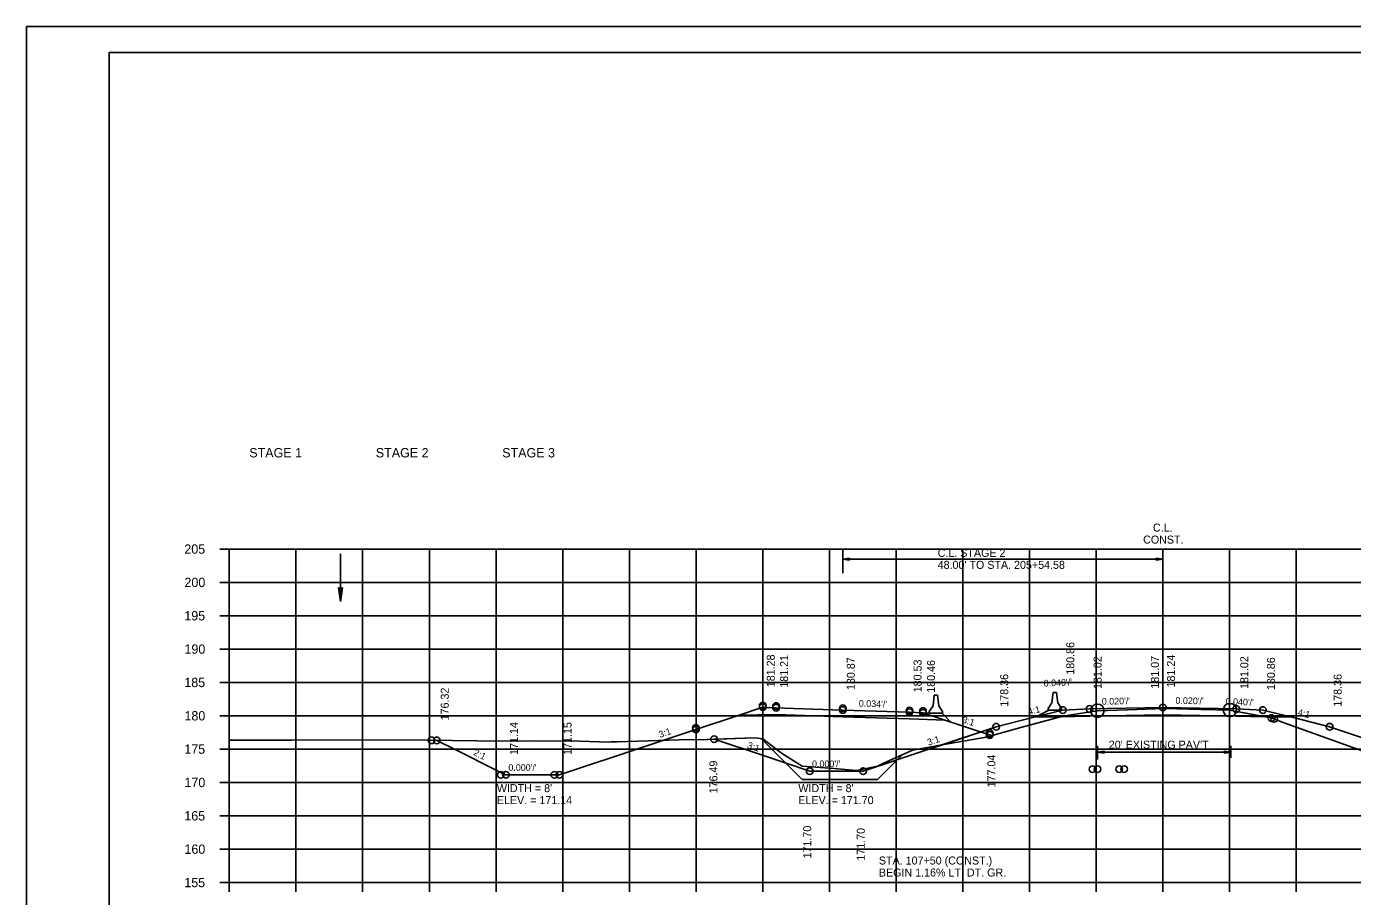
# Model space of a CAD drawing. Extents: x 1372132 to 1372465, y 380083 to 381790.
# Drawn here: x 1372131.6 to 1372330.4, y 381019.7 to 381150.2 of the extents above; entities that cross this region are included whole.
import ezdxf

# ---------------------------------------------------------------- set-up
doc = ezdxf.new("R2010")
doc.units = 0
for name, color, linetype in [('R_Alt Surface', 7, 'Continuous'), ('R_Axis', 7, 'Continuous'), ('R_Axis Annot', 7, 'Continuous'), ('R_Border', 7, 'Continuous'), ('R_Dimension', 7, 'Continuous'), ('R_Draft', 7, 'Continuous'), ('R_Erosion', 7, 'Continuous'), ('R_Exist Surface', 7, 'Continuous'), ('R_Fin Surface', 7, 'Continuous'), ('R_Grid', 7, 'Continuous'), ('R_No Plot', 7, 'Continuous'), ('R_Xsect Elev', 7, 'Continuous'), ('R_Xsect Slope', 7, 'Continuous')]:
    doc.layers.add(name, color=color, linetype=linetype)

msp = doc.modelspace()

# ---------------------------------------------------------------- linework, layer by layer
at = {"layer": 'R_Alt Surface'}
for points in [[(1372269.37, 381046.17), (1372264.02, 381046.35), (1372254.01, 381046.69), (1372244, 381047.04), (1372238.46, 381046.93)], [(1372321.38, 381046.6), (1372313.01, 381046.76), (1372302.01, 381046.98), (1372291.01, 381046.76), (1372282.65, 381046.6)]]:
    msp.add_lwpolyline(points, dxfattribs=at)
at = {"layer": 'R_Axis'}
for p, q in [((1372160.61, 381071.83), (1372162.01, 381071.83)), ((1372162.01, 381021.83), (1372162.01, 381071.83)), ((1372160.61, 381066.83), (1372162.01, 381066.83)), ((1372160.61, 381061.83), (1372162.01, 381061.83)), ((1372160.61, 381056.83), (1372162.01, 381056.83)), ((1372160.61, 381051.83), (1372162.01, 381051.83)), ((1372160.61, 381046.83), (1372162.01, 381046.83)), ((1372160.61, 381041.83), (1372162.01, 381041.83)), ((1372160.61, 381036.83), (1372162.01, 381036.83)), ((1372160.61, 381031.83), (1372162.01, 381031.83)), ((1372160.61, 381026.83), (1372162.01, 381026.83)), ((1372160.61, 381021.83), (1372162.01, 381021.83)), ((1372162.01, 381021.83), (1372442.01, 381021.83)), ((1372162.01, 381020.43), (1372162.01, 381021.83)), ((1372172.01, 381020.43), (1372172.01, 381021.83)), ((1372182.01, 381020.43), (1372182.01, 381021.83)), ((1372192.01, 381020.43), (1372192.01, 381021.83)), ((1372202.01, 381020.43), (1372202.01, 381021.83)), ((1372212.01, 381020.43), (1372212.01, 381021.83)), ((1372222.01, 381020.43), (1372222.01, 381021.83)), ((1372232.01, 381020.43), (1372232.01, 381021.83)), ((1372242.01, 381020.43), (1372242.01, 381021.83)), ((1372252.01, 381020.43), (1372252.01, 381021.83)), ((1372262.01, 381020.43), (1372262.01, 381021.83)), ((1372272.01, 381020.43), (1372272.01, 381021.83)), ((1372282.01, 381020.43), (1372282.01, 381021.83)), ((1372292.01, 381020.43), (1372292.01, 381021.83)), ((1372302.01, 381020.43), (1372302.01, 381021.83)), ((1372312.01, 381020.43), (1372312.01, 381021.83)), ((1372322.01, 381020.43), (1372322.01, 381021.83))]:
    msp.add_line(p, q, dxfattribs=at)
at = {"layer": 'R_Border'}
for p, q in [((1372144.01, 381146.29), (1372460.19, 381146.29)), ((1372144.01, 380940.83), (1372144.01, 381146.29)), ((1372296.53, 381146.03), (1372296.53, 381146.03)), ((1372296.53, 381146.03), (1372296.53, 381146.03))]:
    msp.add_line(p, q, dxfattribs=at)
at = {"layer": 'R_Dimension'}
for p, q in [((1372178.41, 381065.99), (1372178.71, 381063.99)), ((1372179.01, 381065.99), (1372178.41, 381065.99)), ((1372178.41, 381065.99), (1372178.71, 381063.99)), ((1372179.01, 381065.99), (1372178.41, 381065.99)), ((1372178.46, 381065.99), (1372178.71, 381064.32)), ((1372178.46, 381065.99), (1372178.71, 381064.32)), ((1372178.51, 381065.99), (1372178.71, 381064.67)), ((1372178.51, 381065.99), (1372178.71, 381064.67)), ((1372178.56, 381065.99), (1372178.71, 381065)), ((1372178.56, 381065.99), (1372178.71, 381065)), ((1372178.61, 381065.99), (1372178.71, 381065.34)), ((1372178.61, 381065.99), (1372178.71, 381065.34)), ((1372178.66, 381065.99), (1372178.71, 381065.67)), ((1372178.66, 381065.99), (1372178.71, 381065.67)), ((1372179.01, 381065.99), (1372178.71, 381063.99)), ((1372178.8, 381065.99), (1372178.71, 381065.34)), ((1372178.91, 381065.99), (1372178.71, 381064.67)), ((1372178.96, 381065.99), (1372178.71, 381064.32)), ((1372178.86, 381065.99), (1372178.71, 381065)), ((1372178.75, 381065.99), (1372178.71, 381065.67)), ((1372179.01, 381065.99), (1372178.71, 381063.99)), ((1372178.8, 381065.99), (1372178.71, 381065.34)), ((1372178.91, 381065.99), (1372178.71, 381064.67)), ((1372178.96, 381065.99), (1372178.71, 381064.32)), ((1372178.86, 381065.99), (1372178.71, 381065)), ((1372178.75, 381065.99), (1372178.71, 381065.67))]:
    msp.add_line(p, q, dxfattribs=at)
at = {"layer": 'R_Draft'}
for p, q in [((1372178.71, 381071.13), (1372178.71, 381063.99)), ((1372254.01, 381068.23), (1372254.01, 381071.83)), ((1372302.01, 381071.83), (1372302.01, 381068.23)), ((1372255.01, 381070.46), (1372254.01, 381070.31)), ((1372254.01, 381070.31), (1372302.01, 381070.31)), ((1372255.01, 381070.16), (1372254.01, 381070.31)), ((1372255.01, 381070.44), (1372254.18, 381070.31)), ((1372255.01, 381070.19), (1372254.18, 381070.31)), ((1372255.01, 381070.41), (1372254.35, 381070.31)), ((1372255.01, 381070.21), (1372254.35, 381070.31)), ((1372255.01, 381070.39), (1372254.52, 381070.31)), ((1372255.01, 381070.24), (1372254.52, 381070.31)), ((1372255.01, 381070.36), (1372254.69, 381070.31)), ((1372255.01, 381070.27), (1372254.69, 381070.31)), ((1372255.01, 381070.34), (1372254.85, 381070.31)), ((1372255.01, 381070.29), (1372254.85, 381070.31)), ((1372255.01, 381070.16), (1372255.01, 381070.46)), ((1372301.01, 381070.46), (1372302.01, 381070.31)), ((1372301.01, 381070.46), (1372301.01, 381070.16)), ((1372301.01, 381070.46), (1372302.01, 381070.31)), ((1372301.01, 381070.46), (1372301.01, 381070.16)), ((1372301.01, 381070.44), (1372301.85, 381070.31)), ((1372301.01, 381070.44), (1372301.85, 381070.31)), ((1372301.01, 381070.41), (1372301.68, 381070.31)), ((1372301.01, 381070.41), (1372301.68, 381070.31)), ((1372301.01, 381070.39), (1372301.51, 381070.31)), ((1372301.01, 381070.39), (1372301.51, 381070.31)), ((1372301.01, 381070.36), (1372301.34, 381070.31)), ((1372301.01, 381070.36), (1372301.34, 381070.31)), ((1372301.01, 381070.34), (1372301.17, 381070.31)), ((1372301.01, 381070.34), (1372301.17, 381070.31)), ((1372301.01, 381070.16), (1372302.01, 381070.31)), ((1372301.01, 381070.26), (1372301.34, 381070.31)), ((1372301.01, 381070.21), (1372301.68, 381070.31)), ((1372301.01, 381070.19), (1372301.85, 381070.31)), ((1372301.01, 381070.24), (1372301.51, 381070.31)), ((1372301.01, 381070.29), (1372301.17, 381070.31)), ((1372301.01, 381070.16), (1372302.01, 381070.31)), ((1372301.01, 381070.26), (1372301.34, 381070.31)), ((1372301.01, 381070.21), (1372301.68, 381070.31)), ((1372301.01, 381070.19), (1372301.85, 381070.31)), ((1372301.01, 381070.24), (1372301.51, 381070.31)), ((1372301.01, 381070.29), (1372301.17, 381070.31)), ((1372267.72, 381049.9), (1372267.55, 381048.32)), ((1372267.72, 381049.9), (1372268.22, 381049.9)), ((1372268.4, 381048.32), (1372268.22, 381049.9)), ((1372285.55, 381050.34), (1372285.37, 381048.76)), ((1372285.55, 381050.34), (1372286.05, 381050.34)), ((1372286.23, 381048.76), (1372286.05, 381050.34)), ((1372267.55, 381048.32), (1372266.97, 381047.49)), ((1372266.97, 381047.24), (1372266.97, 381047.49)), ((1372266.97, 381047.24), (1372268.97, 381047.24)), ((1372268.97, 381047.49), (1372268.4, 381048.32)), ((1372268.97, 381047.24), (1372268.97, 381047.49)), ((1372285.37, 381048.76), (1372284.8, 381047.92)), ((1372284.8, 381047.67), (1372284.8, 381047.92)), ((1372284.8, 381047.67), (1372286.8, 381047.67)), ((1372286.8, 381047.92), (1372286.23, 381048.76)), ((1372286.8, 381047.67), (1372286.8, 381047.92)), ((1372292.19, 381042.3), (1372292.19, 381040.29)), ((1372293.19, 381041.53), (1372292.19, 381041.38)), ((1372293.19, 381041.53), (1372292.19, 381041.38)), ((1372312.17, 381041.38), (1372292.19, 381041.38)), ((1372293.19, 381041.23), (1372292.19, 381041.38)), ((1372293.19, 381041.23), (1372292.19, 381041.38)), ((1372293.19, 381041.51), (1372292.36, 381041.38)), ((1372293.19, 381041.51), (1372292.36, 381041.38)), ((1372293.19, 381041.26), (1372292.36, 381041.38)), ((1372293.19, 381041.26), (1372292.36, 381041.38)), ((1372293.19, 381041.48), (1372292.53, 381041.38)), ((1372293.19, 381041.48), (1372292.53, 381041.38)), ((1372293.19, 381041.28), (1372292.53, 381041.38)), ((1372293.19, 381041.28), (1372292.53, 381041.38)), ((1372293.19, 381041.46), (1372292.7, 381041.38)), ((1372293.19, 381041.46), (1372292.7, 381041.38)), ((1372293.19, 381041.31), (1372292.7, 381041.38)), ((1372293.19, 381041.31), (1372292.7, 381041.38)), ((1372293.19, 381041.43), (1372292.87, 381041.38)), ((1372293.19, 381041.43), (1372292.87, 381041.38)), ((1372293.19, 381041.33), (1372292.87, 381041.38)), ((1372293.19, 381041.33), (1372292.87, 381041.38)), ((1372293.19, 381041.4), (1372293.03, 381041.38)), ((1372293.19, 381041.4), (1372293.03, 381041.38)), ((1372293.19, 381041.36), (1372293.03, 381041.38)), ((1372293.19, 381041.36), (1372293.03, 381041.38)), ((1372293.19, 381041.23), (1372293.19, 381041.53)), ((1372293.19, 381041.23), (1372293.19, 381041.53)), ((1372311.17, 381041.53), (1372312.17, 381041.38)), ((1372311.17, 381041.53), (1372311.17, 381041.23)), ((1372311.17, 381041.51), (1372312, 381041.38)), ((1372311.17, 381041.48), (1372311.83, 381041.38)), ((1372311.17, 381041.46), (1372311.67, 381041.38)), ((1372311.17, 381041.43), (1372311.5, 381041.38)), ((1372311.17, 381041.4), (1372311.33, 381041.38)), ((1372311.17, 381041.23), (1372312.17, 381041.38)), ((1372311.17, 381041.33), (1372311.5, 381041.38)), ((1372311.17, 381041.28), (1372311.83, 381041.38)), ((1372311.17, 381041.26), (1372312, 381041.38)), ((1372311.17, 381041.31), (1372311.67, 381041.38)), ((1372311.17, 381041.36), (1372311.33, 381041.38)), ((1372312.17, 381042.3), (1372312.17, 381040.52)), ((1372292.19, 381040.52), (1372292.19, 381040.52))]:
    msp.add_line(p, q, dxfattribs=at)
at = {"layer": 'R_Erosion'}
for p, q in [((1372268.95, 381047.15), (1372266.03, 381047.28)), ((1372284.81, 381047.6), (1372283.09, 381046.74)), ((1372287.01, 381047.69), (1372284.81, 381047.6)), ((1372268.95, 381047.15), (1372270.22, 381045.89)), ((1372247.89, 381037.28), (1372241.76, 381043.4)), ((1372259.22, 381037.28), (1372262.92, 381040.98)), ((1372247.89, 381037.28), (1372259.22, 381037.28))]:
    msp.add_line(p, q, dxfattribs=at)
at = {"layer": 'R_Exist Surface'}
msp.add_lwpolyline([(1372162.01, 381043.18), (1372162.71, 381043.18), (1372171.37, 381043.15), (1372182.03, 381043.22), (1372191.65, 381043.16), (1372202.97, 381043.04), (1372207.47, 381043.06), (1372214.53, 381043.01), (1372218.9, 381042.87), (1372219.25, 381042.9), (1372220.16, 381042.9), (1372229.46, 381043.21), (1372233.7, 381043.28), (1372240.81, 381043.52), (1372242.03, 381043.37), (1372244.83, 381041.2), (1372247.9, 381039.27), (1372251.33, 381039.03), (1372252.16, 381038.98), (1372256.01, 381038.65), (1372256.58, 381038.74), (1372259.22, 381039.28), (1372260.03, 381039.65), (1372264.47, 381041.69), (1372268.93, 381042.46), (1372275.51, 381043.64), (1372280.69, 381045.09), (1372286.98, 381046.77), (1372289.51, 381047.15), (1372292.19, 381047.59), (1372296.69, 381047.72), (1372302.23, 381047.9), (1372307.74, 381047.78), (1372312.05, 381047.69), (1372317.93, 381046.57), (1372318.37, 381046.48), (1372320.06, 381045.84), (1372333.14, 381041.1)], dxfattribs=at)
at = {"layer": 'R_Fin Surface'}
for points in [[(1372193.12, 381043.14), (1372193.55, 381042.93), (1372195.57, 381041.92), (1372202.54, 381038.45), (1372203.5, 381037.97), (1372209.96, 381037.97), (1372211.53, 381037.97), (1372224.02, 381042.13), (1372231.99, 381044.78), (1372238.15, 381046.83), (1372242, 381048.11), (1372242.64, 381048.08), (1372244, 381048.04), (1372246.59, 381047.94), (1372254.01, 381047.69), (1372262.29, 381047.41), (1372263.87, 381047.36), (1372264.02, 381047.35), (1372265.95, 381047.29), (1372266.03, 381047.28), (1372274.77, 381044.37), (1372276.04, 381043.95), (1372276.31, 381043.86)], [(1372234.7, 381043.31), (1372241.96, 381040.9), (1372249.04, 381038.53), (1372257.04, 381038.53), (1372267.08, 381041.86), (1372277.01, 381045.19), (1372282.65, 381046.6), (1372287.01, 381047.69), (1372291.01, 381047.85), (1372302.01, 381048.07), (1372313.01, 381047.85), (1372317.01, 381047.69), (1372321.38, 381046.6), (1372327.01, 381045.19), (1372336.47, 381042.02), (1372346.07, 381038.83), (1372350.07, 381038.83), (1372354.63, 381040.37), (1372359.6, 381042.02), (1372359.73, 381042.05)]]:
    msp.add_lwpolyline(points, dxfattribs=at)
at = {"layer": 'R_Grid'}
for p, q in [((1372162.01, 381071.83), (1372442.01, 381071.83)), ((1372162.01, 381021.83), (1372162.01, 381071.83)), ((1372172.01, 381021.83), (1372172.01, 381071.83)), ((1372182.01, 381021.83), (1372182.01, 381071.83)), ((1372192.01, 381021.83), (1372192.01, 381071.83)), ((1372202.01, 381021.83), (1372202.01, 381071.83)), ((1372212.01, 381021.83), (1372212.01, 381071.83)), ((1372222.01, 381021.83), (1372222.01, 381071.83)), ((1372232.01, 381021.83), (1372232.01, 381071.83)), ((1372242.01, 381021.83), (1372242.01, 381071.83)), ((1372252.01, 381021.83), (1372252.01, 381071.83)), ((1372262.01, 381021.83), (1372262.01, 381071.83)), ((1372272.01, 381021.83), (1372272.01, 381071.83)), ((1372282.01, 381021.83), (1372282.01, 381071.83)), ((1372292.01, 381021.83), (1372292.01, 381071.83)), ((1372302.01, 381021.83), (1372302.01, 381071.83)), ((1372312.01, 381021.83), (1372312.01, 381071.83)), ((1372322.01, 381021.83), (1372322.01, 381071.83)), ((1372162.01, 381066.83), (1372442.01, 381066.83)), ((1372162.01, 381061.83), (1372442.01, 381061.83)), ((1372162.01, 381056.83), (1372442.01, 381056.83)), ((1372162.01, 381051.83), (1372442.01, 381051.83)), ((1372162.01, 381046.83), (1372442.01, 381046.83)), ((1372162.01, 381041.83), (1372442.01, 381041.83)), ((1372162.01, 381036.83), (1372442.01, 381036.83)), ((1372162.01, 381031.83), (1372442.01, 381031.83)), ((1372162.01, 381026.83), (1372442.01, 381026.83)), ((1372162.01, 381021.83), (1372442.01, 381021.83))]:
    msp.add_line(p, q, dxfattribs=at)
at = {"layer": 'R_No Plot'}
msp.add_line((1372131.61, 381150.18), (1372464.95, 381150.18), dxfattribs=at)
for points in [[(1372131.61, 381150.18), (1372464.95, 381150.18), (1372464.95, 380936.84), (1372131.61, 380936.84)], [(1372377.93, 381146.29), (1372377.93, 381136.41), (1372413.67, 381136.41), (1372413.67, 381133.49), (1372436.87, 381133.49), (1372436.87, 381109.15), (1372460.19, 381109.15), (1372460.19, 380940.83), (1372144.01, 380940.83), (1372144.01, 381146.29)], [(1372286.64, 381046.68), (1372286.98, 381046.77), (1372289.51, 381047.15), (1372292.19, 381047.59), (1372296.69, 381047.72), (1372302.23, 381047.9), (1372307.74, 381047.78), (1372312.05, 381047.69), (1372317.36, 381046.68), (1372313.01, 381046.76), (1372302.01, 381046.98), (1372291.01, 381046.76)], [(1372268.81, 381042.44), (1372268.93, 381042.46), (1372275.51, 381043.64), (1372280.69, 381045.09), (1372286.64, 381046.68), (1372282.65, 381046.6), (1372277.01, 381045.19)], [(1372317.36, 381046.68), (1372317.93, 381046.57), (1372318.37, 381046.48), (1372320.06, 381045.84), (1372333.14, 381041.1), (1372335.96, 381039.94), (1372337.86, 381039.25), (1372338.93, 381039.46), (1372341.58, 381040.33), (1372336.47, 381042.02), (1372327.01, 381045.19), (1372321.38, 381046.6)], [(1372234.7, 381043.31), (1372240.81, 381043.52), (1372242.03, 381043.37), (1372244.83, 381041.2), (1372247.9, 381039.27), (1372251.33, 381039.03), (1372252.16, 381038.98), (1372256.01, 381038.65), (1372256.58, 381038.74), (1372259.22, 381039.28), (1372260.03, 381039.65), (1372264.47, 381041.69), (1372268.81, 381042.44), (1372267.08, 381041.86), (1372257.04, 381038.53), (1372249.04, 381038.53), (1372241.96, 381040.9)]]:
    msp.add_lwpolyline(points, close=True, dxfattribs=at)
for centre, radius in [((1372242, 381048.36), 0.5), ((1372242, 381048.11), 0.5), ((1372244, 381048.29), 0.5), ((1372244, 381048.04), 0.5), ((1372254.01, 381047.95), 0.5), ((1372254.01, 381047.69), 0.5), ((1372264.02, 381047.6), 0.5), ((1372264.02, 381047.35), 0.5), ((1372266.03, 381047.54), 0.5), ((1372266.03, 381047.28), 0.5), ((1372287.01, 381047.69), 0.5), ((1372291.01, 381047.85), 0.5), ((1372292.19, 381047.59), 1), ((1372302.01, 381048.07), 0.5), ((1372312.05, 381047.69), 1), ((1372313.01, 381047.85), 0.5), ((1372317.01, 381047.69), 0.5), ((1372231.99, 381045.03), 0.5), ((1372231.99, 381044.78), 0.5), ((1372277.01, 381045.19), 0.5), ((1372318.31, 381046.49), 0.5), ((1372318.7, 381046.37), 0.5), ((1372327.01, 381045.19), 0.5), ((1372192.34, 381043.15), 0.5), ((1372193.12, 381043.14), 0.5), ((1372234.7, 381043.31), 0.5), ((1372276.04, 381044.2), 0.5), ((1372276.04, 381043.95), 0.5), ((1372291.45, 381038.82), 0.5), ((1372292.21, 381038.82), 0.5), ((1372295.44, 381038.83), 0.5), ((1372296.2, 381038.83), 0.5), ((1372202.74, 381037.97), 0.5), ((1372203.5, 381037.97), 0.5), ((1372210.76, 381037.97), 0.5), ((1372211.53, 381037.97), 0.5), ((1372249.04, 381038.53), 0.5), ((1372257.04, 381038.53), 0.5)]:
    msp.add_circle(centre, radius, dxfattribs=at)
at = {"layer": 'R_Xsect Elev'}
msp.add_line((1372302.01, 381047.9), (1372302.01, 381057.9), dxfattribs=at)

# ---------------------------------------------------------------- texts
at = {"layer": 'R_Axis Annot'}
for s, p in [('STAGE 1', (1372165.01, 381085.57)), ('STAGE 2', (1372183.98, 381085.57)), ('STAGE 3', (1372202.94, 381085.57)), ('205', (1372155.27, 381071.13)), ('200', (1372155.29, 381066.13)), ('195', (1372155.27, 381061.13)), ('190', (1372155.29, 381056.13)), ('185', (1372155.27, 381051.13)), ('180', (1372155.29, 381046.13)), ('175', (1372155.27, 381041.13)), ('170', (1372155.29, 381036.13)), ('165', (1372155.27, 381031.13)), ('160', (1372155.29, 381026.13)), ('155', (1372155.27, 381021.13))]:
    msp.add_text(s, height=1.4, dxfattribs=at).set_placement(p)
at = {"layer": 'R_Dimension'}
for s, p in [("WIDTH = 8'", (1372202.13, 381035.38)), ("WIDTH = 8'", (1372247.34, 381035.38)), ('ELEV. = 171.14', (1372202.13, 381033.58)), ('ELEV. = 171.70', (1372247.34, 381033.58))]:
    msp.add_text(s, height=1.2, dxfattribs=at).set_placement(p)
at = {"layer": 'R_Draft'}
for s, p in [('C.L. ', (1372300.51, 381074.45)), ('CONST. ', (1372299.04, 381072.65)), ('C.L. STAGE 2', (1372268.23, 381070.66)), ("48.00' TO STA. 205+54.58", (1372268.23, 381068.86)), ("20' EXISTING PAV'T", (1372293.89, 381041.9))]:
    msp.add_text(s, height=1.2, rotation=360, dxfattribs=at).set_placement(p)
for s, p in [('STA. 107+50 (CONST.)', (1372259.42, 381024.53)), ('BEGIN 1.16% LT. DT. GR.', (1372259.42, 381022.73))]:
    msp.add_text(s, height=1.2, dxfattribs=at).set_placement(p)
at = {"layer": 'R_Xsect Elev'}
for s, p in [('180.86', (1372288.72, 381052.99)), ('181.28', (1372243.8, 381051.11)), ('181.21', (1372245.8, 381051.04)), ('180.87', (1372255.81, 381050.69)), ('180.53', (1372265.82, 381050.35)), ('181.02', (1372292.81, 381050.85)), ('181.07', (1372301.41, 381050.9)), ('181.24', (1372303.81, 381051.07)), ('181.02', (1372314.81, 381050.85)), ('180.86', (1372318.81, 381050.69)), ('180.46', (1372267.83, 381050.28)), ('178.36', (1372278.81, 381048.19)), ('178.36', (1372328.81, 381048.19)), ('176.32', (1372194.92, 381046.14)), ('171.14', (1372205.3, 381040.97)), ('171.15', (1372213.33, 381040.97)), ('176.49', (1372235.2, 381035.2)), ('177.04', (1372276.89, 381036.09)), ('171.70', (1372249.27, 381025.44)), ('171.70', (1372257.3, 381025.1))]:
    msp.add_text(s, height=1.2, rotation=90, dxfattribs=at).set_placement(p)
at = {"layer": 'R_Xsect Slope'}
for s, rotation, p in [("0.040'/'", 2.2906, (1372284.15, 381051.21)), ("0.020'/'", 1.1458, (1372292.85, 381048.48)), ("0.020'/'", 358.8542, (1372303.88, 381048.63)), ("0.040'/'", 357.7094, (1372311.39, 381048.51)), ("0.034'/'", 358.0514, (1372256.39, 381048.21)), ('4:1', 14.0362, (1372281.89, 381046.92)), ('4:1', 345.9638, (1372322.14, 381046.92)), ('3:1', 341.5945, (1372271.81, 381045.84)), ('3:1', 18.3974, (1372226.6, 381043.51)), ('3:1', 18.4332, (1372266.87, 381042.33)), ('2:1', 333.5094, (1372198.53, 381041)), ('3:1', 341.5651, (1372239.59, 381042.01)), ("0.000'/'", 0.0149, (1372203.86, 381038.57)), ("0.000'/'", 360, (1372249.39, 381039.13))]:
    msp.add_text(s, height=1, rotation=rotation, dxfattribs=at).set_placement(p)

doc.saveas('drawing.dxf')
